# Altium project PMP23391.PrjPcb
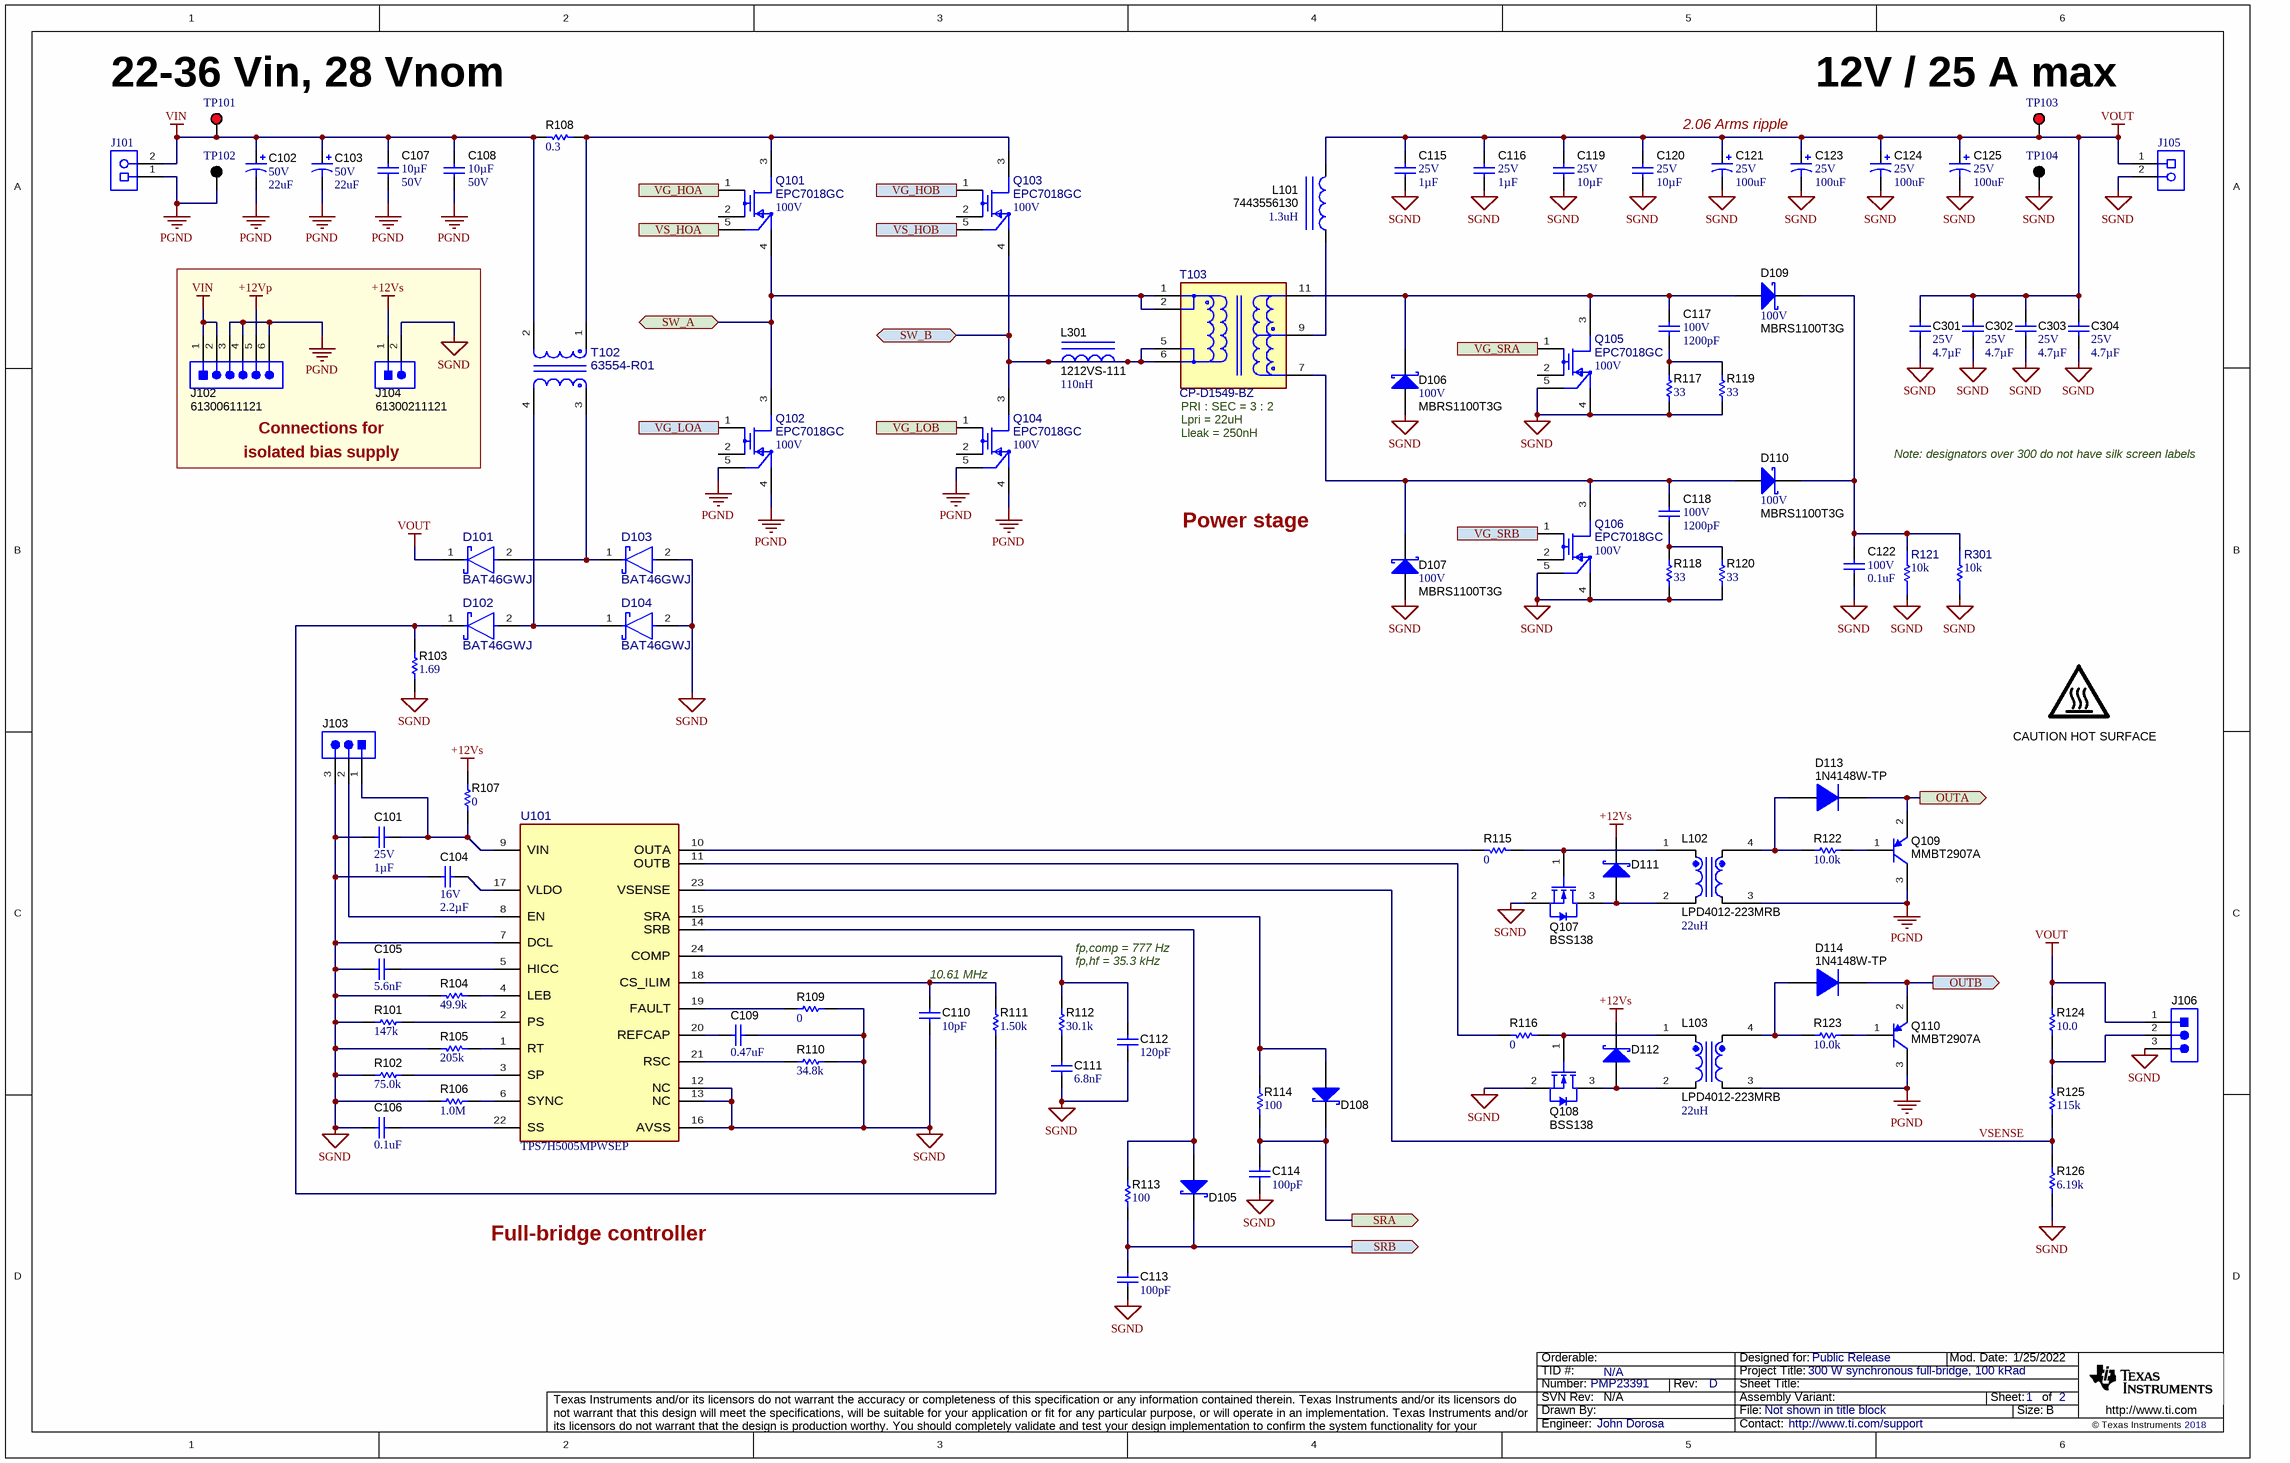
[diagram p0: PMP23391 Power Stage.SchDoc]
TID: N/A; TechSupport: http://www.ti.com/support; SCH_Rev: D; PRJ_Title: 300 W synchronous full-bridge, 100 kRad; PRJ_Number: PMP23391; PRJ_Engineer: John Dorosa; PRJ_Customer: Public Release; PCB_Rev: C; PCB_Layout: John Dorosa; CopyrightYear: 2018
2 sheets, 165 parts. Net scope: flat (ports and power ports of the same name join across sheets).
Board file: PMP23391.PcbDoc
Sheets:
  PMP23391 Power Stage.SchDoc
  PMP23391 Drivers.SchDoc

## Sheet PMP23391 Power Stage.SchDoc
size 431 x 279 mm; Date: Not shown in title block; ApprovedBy: Not shown in title block; CheckedBy: Not shown in title block; Author: Not shown in title block; CompanyName: Not shown in title block; Engineer: Not shown in title block; Organization: Not shown in title block; Address1: Not shown in title block; Address2: Not shown in title block; Address3: Not shown in title block; Address4: Not shown in title block; DocumentNumber: 1; Revision: Use project parameter SCH_Rev; SheetNumber: 1; SheetTotal: 2; PageSetup: Record=PageOptions¦CenterHorizontal=True¦CenterVertical=True¦PrintScale=1.00¦XCorrection=1.00¦YCorrection=1.00¦PrintKind=0¦BorderSize=5000000¦LeftOffset=0¦BottomOffset=0¦Orientation=2¦PaperLength=1000¦PaperWidth=1000¦Scale=100¦PaperSource=15¦PrintQuality=600¦MediaType=1¦DitherType=10¦PaperKind=Letter¦PrintScaleMode=1

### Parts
C101  VDC_V: 25V  Cap_F: 1µF  [0603_HV]  (hidden comment: GRM188R71E105KA12D)
C102  VDC_V: 50V  ValueDisplayed: 22uF  [7343-43]  (hidden comment: T494X226K050AT)
C103  VDC_V: 50V  ValueDisplayed: 22uF  [7343-43]  (hidden comment: T494X226K050AT)
C104  VDC_V: 16V  Cap_F: 2.2µF  [0603_HV]  (hidden comment: GRM188Z71C225KE43)
C105  Cap_F: 5.6nF  [0603_HV]  (hidden comment: GRM188R71E562KA01D)
C106  value 0.1uF  [0603_HV]  (hidden comment: GCM188R71E104KA57D)
C107  ValueDisplayed: 10µF  VDC_V: 50V  [1210_270]  (hidden comment: GCM32EL8EH106KA07L)
C108  ValueDisplayed: 10µF  VDC_V: 50V  [1210_270]  (hidden comment: GCM32EL8EH106KA07L)
C109  value 0.47uF  [0603_HV]  (hidden comment: GCM188R71C474KA55D)
C110  ValueDisplayed: 10pF  [0603_HV]  (hidden comment: GCM1885C2A100JA16D)
C111  Cap_F: 6.8nF  [0603_HV]  (hidden comment: GRM188R71E682KA01D)
C112  ValueDisplayed: 120pF  [0603_HV]  (hidden comment: GRM1885C1H121JA01D)
C113  ValueDisplayed: 100pF  [0603_HV]  (hidden comment: GRM1885C1H101JA01D)
C114  ValueDisplayed: 100pF  [0603_HV]  (hidden comment: GRM1885C1H101JA01D)
C115  VDC_V: 25V  Cap_F: 1µF  [0603_HV]  (hidden comment: GRM188R71E105KA12D)
C116  VDC_V: 25V  Cap_F: 1µF  [0603_HV]  (hidden comment: GRM188R71E105KA12D)
C117  VDC_V: 100V  ValueDisplayed: 1200pF  [0805_HV]  (hidden comment: GRM2165C2A122JA01D)
C118  VDC_V: 100V  ValueDisplayed: 1200pF  [0805_HV]  (hidden comment: GRM2165C2A122JA01D)
C119  VDC_V: 25V  ValueDisplayed: 10µF  [1206]  (hidden comment: GRM31CR71E106MA12L)
C120  VDC_V: 25V  ValueDisplayed: 10µF  [1206]  (hidden comment: GRM31CR71E106MA12L)
C121  VDC_V: 25V  ValueDisplayed: 100uF  [7361-38]  (hidden comment: TPSV107K025R0100)
C122  VDC_V: 100V  ValueDisplayed: 0.1uF  [1206]  (hidden comment: GRM319R72A104KA01D)
C123  VDC_V: 25V  ValueDisplayed: 100uF  [7361-38]  (hidden comment: TPSV107K025R0100)
C124  VDC_V: 25V  ValueDisplayed: 100uF  [7361-38]  (hidden comment: TPSV107K025R0100)
C125  VDC_V: 25V  ValueDisplayed: 100uF  [7361-38]  (hidden comment: TPSV107K025R0100)
C301  VDC_V: 25V  Cap_F: 4.7µF  [0805_HV]  (hidden comment: GRM21BR71E475KA73L)
C302  VDC_V: 25V  Cap_F: 4.7µF  [0805_HV]  (hidden comment: GRM21BR71E475KA73L)
C303  VDC_V: 25V  Cap_F: 4.7µF  [0805_HV]  (hidden comment: GRM21BR71E475KA73L)
C304  VDC_V: 25V  Cap_F: 4.7µF  [0805_HV]  (hidden comment: GRM21BR71E475KA73L)
D101  BAT46GWJ  [FP-BAT46GWJ_SOD-123-MFG]
D102  BAT46GWJ  [FP-BAT46GWJ_SOD-123-MFG]
D103  BAT46GWJ  [FP-BAT46GWJ_SOD-123-MFG]
D104  BAT46GWJ  [FP-BAT46GWJ_SOD-123-MFG]
D105  PMEG4030ER,115  [SOD-123W]  (value not drawn)
D106  MBRS1100T3G  value 100V  [SMB]
D107  MBRS1100T3G  value 100V  [SMB]
D108  PMEG4030ER,115  [SOD-123W]  (value not drawn)
D109  MBRS1100T3G  value 100V  [SMB]
D110  MBRS1100T3G  value 100V  [SMB]
D111  PMEG4030ER,115  [SOD-123W]  (value not drawn)
D112  PMEG4030ER,115  [SOD-123W]  (value not drawn)
D113  1N4148W-TP  [SOD-123]
D114  1N4148W-TP  [SOD-123]
J101  OSTT7020150  [On-Shore_OSTT7020150]  (value not drawn)
J102  61300611121  [WURTH_61300611121]
J103  61300311121  [WURTH_61300311121]  (value not drawn)
J104  61300211121  [WURTH_61300211121]
J105  OSTT7020150  [On-Shore_OSTT7020150]  (value not drawn)
J106  61300311121  [WURTH_61300311121]  (value not drawn)
L101  7443556130  ValueDisplayed: 1.3uH  [WE-HCB_1890]
L102  LPD4012-223MRB  ValueDisplayed: 22uH  [LPD4012]
L103  LPD4012-223MRB  ValueDisplayed: 22uH  [LPD4012]
L301  1212VS-111  ValueDisplayed: 110nH  [SLC1480]
Logo101  CAUTION HOT SURFACE  [IEC_HotSurface_Small]  (no BOM)
Q101  EPC7018GC  VdsMax_V: 100V  [FP-EPC7018GC_FSMD-G-MFG]
Q102  EPC7018GC  VdsMax_V: 100V  [FP-EPC7018GC_FSMD-G-MFG]
Q103  EPC7018GC  VdsMax_V: 100V  [FP-EPC7018GC_FSMD-G-MFG]
Q104  EPC7018GC  VdsMax_V: 100V  [FP-EPC7018GC_FSMD-G-MFG]
Q105  EPC7018GC  VdsMax_V: 100V  [FP-EPC7018GC_FSMD-G-MFG]
Q106  EPC7018GC  VdsMax_V: 100V  [FP-EPC7018GC_FSMD-G-MFG]
Q107  BSS138  [SOT-23]
Q108  BSS138  [SOT-23]
Q109  MMBT2907A  [SOT-23]
Q110  MMBT2907A  [SOT-23]
R101  ValueDisplayed: 147k  [0603_HV]  (hidden comment: CRCW0603147KFKEA)
R102  ValueDisplayed: 75.0k  [0603_HV]  (hidden comment: CRCW060375K0FKEA)
R103  ValueDisplayed: 1.69  [1206]  (hidden comment: CRCW12061R69FKEA)
R104  ValueDisplayed: 49.9k  [0603_HV]  (hidden comment: CRCW060349K9FKEA)
R105  ValueDisplayed: 205k  [0603_HV]  (hidden comment: RC0603FR-07205KL)
R106  ValueDisplayed: 1.0M  [0603_HV]  (hidden comment: CRCW06031M00JNEA)
R107  ValueDisplayed: 0  [0603_HV]  (hidden comment: CRCW06030000Z0EA)
R108  ValueDisplayed: 0.3  [1210]  (hidden comment: MCR25JZHFLR300)
R109  ValueDisplayed: 0  [0603_HV]  (hidden comment: CRCW06030000Z0EA)
R110  ValueDisplayed: 34.8k  [0603_HV]  (hidden comment: CRCW060334K8FKEA)
R111  ValueDisplayed: 1.50k  [0603_HV]  (hidden comment: CRCW06031K50FKEA)
R112  ValueDisplayed: 30.1k  [0603_HV]  (hidden comment: CRCW060330K1FKEA)
R113  ValueDisplayed: 100  [0603_HV]  (hidden comment: CRCW0603100RJNEA)
R114  ValueDisplayed: 100  [0603_HV]  (hidden comment: CRCW0603100RJNEA)
R115  ValueDisplayed: 0  [0805_HV1]  (hidden comment: RC0805JR-070RL)
R116  ValueDisplayed: 0  [0805_HV1]  (hidden comment: RC0805JR-070RL)
R117  ValueDisplayed: 33  [2512]  (hidden comment: CRCW251233R0JNEG)
R118  ValueDisplayed: 33  [2512]  (hidden comment: CRCW251233R0JNEG)
R119  ValueDisplayed: 33  [2512]  (hidden comment: CRCW251233R0JNEG)
R120  ValueDisplayed: 33  [2512]  (hidden comment: CRCW251233R0JNEG)
R121  value 10k  [FP-CRM2512-FX-1002ELF_2512-MFG]  (hidden comment: CRM2512-FX-1002ELF)
R122  ValueDisplayed: 10.0k  [0603_HV]  (hidden comment: CRCW060310K0FKEA)
R123  ValueDisplayed: 10.0k  [0603_HV]  (hidden comment: CRCW060310K0FKEA)
R124  ValueDisplayed: 10.0  [0603_HV]  (hidden comment: CRCW060310R0FKEA)
R125  ValueDisplayed: 115k  [0603_HV]  (hidden comment: CRCW0603115KFKEA)
R126  ValueDisplayed: 6.19k  [0603_HV]  (hidden comment: CRCW06036K19FKEA)
R301  value 10k  [FP-CRM2512-FX-1002ELF_2512-MFG]  (hidden comment: CRM2512-FX-1002ELF)
T102  63554-R01  [FP-63554-R01_SMT_XFRMR_24MM0_20MM0-MFG]
T103  CP-D1549-BZ  [FP-CP-D1549-BZ_SMT_XFRMR_29MM46_26MM67-MFG]
TP101  5010  [Keystone5010]  (value not drawn)
TP102  5011  [Keystone5011]  (value not drawn)
TP103  5010  [Keystone5010]  (value not drawn)
TP104  5011  [Keystone5011]  (value not drawn)
U101  TPS7H5005MPWSEP  [PW0024A-MFG]

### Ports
OUTA (out), OUTB (out), SRA (out), SRB (out), SW_A (bidir), SW_B (bidir), VG_HOA (in), VG_HOB (in), VG_LOA (in), VG_LOB (in), VG_SRA (in), VG_SRB (in), VS_HOA (in), VS_HOB (in)

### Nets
+12Vp: J102.5
+12Vs: D111.1(K) D112.1(K) J104.1 R107.2
PGND: C102.2(-) C103.2(-) C107.2 C108.2 J101.1 J102.3 J102.4 J102.6 L102.3 L103.3 Q102.4(S) Q102.5(SS) Q104.4(S) Q104.5(SS) Q109.3(C) Q110.3(C) TP102.1
SGND: C101.2 C104.1 C105.1 C106.2 C109.1 C110.2 C111.2 C112.2 C113.1 C114.1 C115.2 C116.2 C119.2 C120.2 C121.2(-) C122.2 C123.2(-) C124.2(-) C125.2(-) C301.2 C302.2 C303.2 C304.2 D103.2(ANODE) D104.2(ANODE) D106.2(A) D107.2(A) J103.3 J104.2 J105.2 J106.3 Q105.4(S) Q105.5(SS) Q106.4(S) Q106.5(SS) Q107.2(S) Q108.2(S) R101.1 R102.1 R103.1 R104.2 R105.2 R106.1 R109.2 R110.2 R117.1 R118.1 R119.1 R120.1 R121.2 R126.1 R301.2 TP104.1 U101.7(DCL) U101.12(NC) U101.13(NC) U101.16(AVSS)
VIN: C102.1(+) C103.1(+) C107.1 C108.1 J101.2 J102.1 J102.2 R108.1 T102.2 TP101.1
VOUT: C115.1 C116.1 C119.1 C120.1 C121.1(+) C123.1(+) C124.1(+) C125.1(+) C301.1 C302.1 C303.1 C304.1 D101.1(CATHODE) J105.1 J106.1 L101.2 R124.2 TP103.1
OUTA: D113.1(K) Q109.2(E) ; port OUTA
OUTB: D114.1(K) Q110.2(E) ; port OUTB
SRA: C114.2 D108.1(K) R114.1 ; port SRA
SRB: C113.2 D105.1(K) R113.1 ; port SRB
SW_A: Q101.4(S) Q102.3(D) T103.1 T103.2 ; port SW_A
SW_B: L301.1 L301.2 Q103.4(S) Q104.3(D) T103.5 T103.6 ; port SW_B
VG_HOA: Q101.1(G) ; port VG_HOA
VG_HOB: Q103.1(G) ; port VG_HOB
VG_LOA: Q102.1(G) ; port VG_LOA
VG_LOB: Q104.1(G) ; port VG_LOB
VG_SRA: Q105.1(G) ; port VG_SRA
VG_SRB: Q106.1(G) ; port VG_SRB
VS_HOA: Q101.5(SS) ; port VS_HOA
VS_HOB: Q103.5(SS) ; port VS_HOB
VSENSE: R125.1 R126.2 U101.23(VSENSE)
NetC101_1: C101.1 J103.1 R107.1 U101.9(VIN)
NetC104_2: C104.2 U101.17(VLDO)
NetC105_2: C105.2 U101.5(HICC)
NetC106_1: C106.1 U101.22(SS)
NetC109_2: C109.2 U101.20(REFCAP)
NetC110_1: C110.1 R111.1 U101.18(CS_ILIM)
NetC111_1: C111.1 R112.1
NetC112_1: C112.1 R112.2 U101.24(COMP)
NetC117_1: C117.1 D106.1(K) D109.2(A) Q105.3(D) T103.11
NetC117_2: C117.2 R117.2 R119.2
NetC118_1: C118.1 D107.1(K) D110.2(A) Q106.3(D) T103.7
NetC118_2: C118.2 R118.2 R120.2
NetC122_1: C122.1 D109.1(K) D110.1(K) R121.1 R301.1
NetD101_2: D101.2(ANODE) D103.1(CATHODE) T102.3
NetD102_1: D102.1(CATHODE) R103.2 R111.2
NetD102_2: D102.2(ANODE) D104.1(CATHODE) T102.4
NetD105_2: D105.2(A) R113.2 U101.14(SRB)
NetD108_2: D108.2(A) R114.2 U101.15(SRA)
NetD111_2: D111.2(A) L102.2 Q107.3(D)
NetD112_2: D112.2(A) L103.2 Q108.3(D)
NetD113_2: D113.2(A) L102.4 R122.2
NetD114_2: D114.2(A) L103.4 R123.2
NetJ103_2: J103.2 U101.8(EN)
NetJ106_2: J106.2 R124.1 R125.2
NetL101_1: L101.1 T103.9
NetL102_1: L102.1 Q107.1(G) R115.1
NetL103_1: L103.1 Q108.1(G) R116.1
NetQ101_3: Q101.3(D) Q103.3(D) R108.2 T102.1
NetQ109_1: Q109.1(B) R122.1
NetQ110_1: Q110.1(B) R123.1
NetR101_2: R101.2 U101.2(PS)
NetR102_2: R102.2 U101.3(SP)
NetR104_1: R104.1 U101.4(LEB)
NetR105_1: R105.1 U101.1(RT)
NetR106_2: R106.2 U101.6(SYNC)
NetR109_1: R109.1 U101.19(FAULT)
NetR110_1: R110.1 U101.21(RSC)
NetR115_2: R115.2 U101.10(OUTA)
NetR116_2: R116.2 U101.11(OUTB)

Not connected (* = marked no-connect by the designer): Q101 2(G); Q102 2(G); Q103 2(G); Q104 2(G); Q105 2(G); Q106 2(G)

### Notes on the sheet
- (near TP101) 22-36 Vin, 28 Vnom
- (near TP103) 12V / 25 A max
- 2.06 Arms ripple
- Connections for
- (near T103) PRI : SEC = 3 : 2
- (near T103) Lpri = 22uH
- isolated bias supply
- Lleak = 250nH
- Note: designators over 300 do not have silk screen labels
- Power stage
- fp,comp = 777 Hz
- 10.61 MHz
- fp,hf = 35.3 kHz
- Full-bridge controller

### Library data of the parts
C101 C115 C116 = CMP-0007405-5: CAP, CERM, 1 uF, 25 V, +/- 10%, X7R, 0603; Manufacturer: MuRata; Cap_Case: 0603; AEC Category: Q200; Value: 1uF; SizeX_mm: 1.6; U/M: EA; Value1: Unknown; SizeAreaWB_mm2: 4.68; SizeY_mm: 0.8; TaMin_C: -55°C; SizeZ_mm: 1; Polarized: N; MFG_Status: TI_Obsolete; TaMax_C: 125°C; SizeArea_mm2: 1.28
C102 C103 = CMP-0011753-2: CAP, TA, 22 uF, 50 V, +/- 10%, 0.5 ohm, SMD; Manufacturer: Kemet; TaMin_C: -55°C; ESR_ohm: 0.5; Polarized: Y; SizeAreaWB_mm2: 58.59; Value1: 0.5 ohm; U/M: EA; Value: 22uF; TaMax_C: 125°C; SizeZ_mm: 4.3; SizeX_mm: 7.3; SizeArea_mm2: 31.39; CompType: Capacitor; AEC Qualified: N; Cap_F: 22µF; IRMS_A: 574mA; AEC Category: Q200
C104 = CMP-0007499-4: CAP, CERM, 2.2 uF, 16 V, +/- 10%, X7R, 0603; Manufacturer: MuRata; TaMin_C: -55°C; Polarized: N; SizeAreaWB_mm2: 4.68; Value1: Unknown; U/M: EA; Value: 2.2uF; TaMax_C: 125°C; SizeZ_mm: 1; SizeX_mm: 1.6; SizeY_mm: 0.8; Cap_Case: 0603; SizeArea_mm2: 1.28; AEC Category: Q200
C105 = CMP-0007425-5: CAP, CERM, 5600 pF, 25 V, +/- 10%, X7R, 0603; Manufacturer: MuRata; ValueDisplayed: 5600pF; SizeArea_mm2: 1.28; SizeZ_mm: 1; Value2: 25V; MFG_Status: TI_Obsolete; SizeX_mm: 1.6; Value1: Unknown; AEC Category: Q200; Value: 5600pF; SizeAreaWB_mm2: 4.68; Polarized: N; Cap_Case: 0603; U/M: EA; TaMin_C: -55°C; TaMax_C: 125°C; SizeY_mm: 0.8
C106 = CMP-0084679-1: CAP, CERM, 0.1 µF, 25 V,+/- 10%, X7R, AEC-Q200 Grade 1, 0603; Manufacturer: MuRata; VDC_V: 25V; TaMin_C: -55°C; SizeY_mm: 0.8; Polarized: N; SizeArea_mm2: 1.28; Cap_Case: 0603; SizeZ_mm: 1; SizeX_mm: 1.6; AEC Qualified: Y; AEC Category: Q200; ValueDisplayed: 0.1µF; TaMax_C: 125°C; U/M: EA; SizeAreaWB_mm2: 4.68; Cap_F: 100nF
C107 C108 = CMP-0860266-1: CAP, CERM, 10 µF, 50 V,+/- 10%, X8L, AEC-Q200 Grade 0, 1210; Manufacturer: MuRata; Value: 10uF; U/M: EA; SizeY_mm: 2.5; Polarized: N; AEC Category: Q200; SizeZ_mm: 2.7; TaMin_C: -55°C; AEC Qualified: Y; TaMax_C: 150°C; Cap_Case: 1210; SizeArea_mm2: 8; SizeAreaWB_mm2: 14.7; AEC Grade: 0; SizeX_mm: 3.2
C109 = CMP-0007138-4: CAP, CERM, 0.47 uF, 16 V, +/- 10%, X7R, AEC-Q200 Grade 1, 0603; Manufacturer: MuRata; TaMin_C: -55°C; Polarized: N; SizeAreaWB_mm2: 4.68; Value1: Unknown; U/M: EA; TaMax_C: 125°C; SizeZ_mm: 1; SizeX_mm: 1.6; SizeY_mm: 0.8; Cap_Case: 0603; Value2: 16V; SizeArea_mm2: 1.28; AEC Qualified: Y; Cap_F: 470nF; AEC Category: Q200
C110 = CMP-0084283-1: CAP, CERM, 10 pF, 100 V,+/- 5%, C0G/NP0, AEC-Q200 Grade 1, 0603; Manufacturer: MuRata; TaMax_C: 125°C; Cap_Case: 0603; Value2: 100V; SizeX_mm: 1.6; SizeY_mm: 0.8; SizeArea_mm2: 1.28; Polarized: N; AEC Category: Q200; SizeAreaWB_mm2: 4.68; AEC Qualified: Y; SizeZ_mm: 1; Value: 10pF; U/M: EA; TaMin_C: -55°C
C111 = CMP-0007427-5: CAP, CERM, 6800 pF, 25 V, +/- 10%, X7R, 0603; Manufacturer: MuRata; Value1: Unknown; MFG_Status: TI_Obsolete; SizeY_mm: 0.8; TaMin_C: -55°C; Value2: 25V; U/M: EA; SizeAreaWB_mm2: 4.68; SizeArea_mm2: 1.28; AEC Category: Q200; SizeZ_mm: 1; ValueDisplayed: 6800pF; Polarized: N; SizeX_mm: 1.6; TaMax_C: 125°C; Cap_Case: 0603; Value: 6800pF
C112 = CMP-0007179-4: CAP, CERM, 120 pF, 50 V, +/- 5%, C0G/NP0, 0603; Manufacturer: MuRata; TaMin_C: -55°C; Polarized: N; SizeAreaWB_mm2: 4.68; Value1: Unknown; U/M: EA; Value: 120pF; TaMax_C: 125°C; SizeZ_mm: 1; SizeX_mm: 1.6; SizeY_mm: 0.8; Cap_Case: 0603; Value2: 50V; SizeArea_mm2: 1.28; AEC Category: Q200
C113 C114 = CMP-0007171-4: CAP, CERM, 100 pF, 50 V, +/- 5%, C0G/NP0, 0603; Manufacturer: MuRata; TaMin_C: -55°C; Polarized: N; SizeAreaWB_mm2: 4.68; Value1: Unknown; U/M: EA; Value: 100pF; TaMax_C: 125°C; SizeZ_mm: 1; SizeX_mm: 1.6; SizeY_mm: 0.8; Cap_Case: 0603; Value2: 50V; SizeArea_mm2: 1.28; AEC Category: Q200
C117 C118 = CMP-0008098-2: CAP, CERM, 1200 pF, 100 V, +/- 5%, C0G/NP0, 0805; Manufacturer: MuRata; TaMin_C: -55°C; Polarized: N; SizeAreaWB_mm2: 6.75; Value1: Unknown; U/M: EA; Value: 1200pF; TaMax_C: 125°C; SizeZ_mm: 1.45; SizeX_mm: 2; SizeY_mm: 1.25; Cap_Case: 0805; SizeArea_mm2: 2.5; Cap_F: 1.2nF; AEC Category: Q200
C119 C120 = CMP-0082252-1: CAP, CERM, 10 µF, 25 V,+/- 20%, X7R, AEC-Q200 Grade 1, 1206; Manufacturer: MuRata; SizeAreaWB_mm2: 10.92; SizeArea_mm2: 5.12; AEC Qualified: Y; AEC Category: Q200; Value: 10uF; TaMax_C: 125°C; SizeZ_mm: 1.35; AEC Grade: 1; Polarized: N; TaMin_C: -55°C; SizeY_mm: 1.6; U/M: EA; SizeX_mm: 3.2
C121 C123-C125 = CMP-0012041-2: CAP, TA, 100 uF, 25 V, +/- 10%, 0.1 ohm, SMD; Manufacturer: AVX; TaMin_C: -55°C; ESR_ohm: 0.1; Polarized: Y; SizeAreaWB_mm2: 75.33; Value1: 0.1 ohm; U/M: EA; Value: 100uF; TaMax_C: 125°C; SizeZ_mm: 3.8; SizeX_mm: 7.3; SizeY_mm: 6.1; SizeArea_mm2: 44.53; CompType: Capacitor; Cap_F: 100µF; IRMS_A: 1.423A; AEC Category: Q200
C122 = CMP-0008881-2: CAP, CERM, 0.1 uF, 100 V, +/- 10%, X7R, 1206; Manufacturer: MuRata; TaMin_C: -55°C; Polarized: N; SizeAreaWB_mm2: 10.92; Value1: Unknown; U/M: EA; Value: 0.1uF; TaMax_C: 125°C; SizeZ_mm: 1.35; SizeX_mm: 3.2; SizeY_mm: 1.6; SizeArea_mm2: 5.12; Cap_F: 100nF; AEC Category: Q200
C301-C304 = CMP-0008346-3: CAP, CERM, 4.7 uF, 25 V, +/- 10%, X7R, 0805; Manufacturer: MuRata; TaMax_C: 125°C; SizeZ_mm: 1.45; Value1: Unknown; Polarized: N; SizeY_mm: 1.25; TaMin_C: -55°C; SizeX_mm: 2; SizeAreaWB_mm2: 6.75; MFG_Status: TI_Obsolete; SizeArea_mm2: 2.5; AEC Category: Q200; Cap_Case: 0805; Value: 4.7uF; U/M: EA
D101-D104 = CMP-0090343-1: Diode Schottky 100V 250mA (DC) Surface Mount SOD-123; Manufacturer: Nexperia; SizeZ_mm: 1.3mm; Peak Reverse Current: 2uA; TaMin_C: -55°C; Cap_F: 39pF; TJmax_C: 150°C; AEC Grade: Grade 0; Max Surge Forward Current: 2.5A; Standoff Height: 0mm; TaMax_C: +150°C; AEC Qualified: Yes
D105 D108 D111 D112 = CMP-0080763-2: Diode, Schottky, 40 V, 3 A, AEC-Q101, SOD-123W; Manufacturer: Nexperia; Value2: 0.54V; AEC Category: Q101; SizeArea_mm2: 5.95; AEC Qualified: Y; Io_A: 3A; SizeZ_mm: 1; Value: 40V; SizeY_mm: 1.7; Vf_V: 540mV; SizeAreaWB_mm2: 12.15; SizeX_mm: 3.5; TJmax_C: 150°C
D106 D107 D109 D110 = CMP-0028521-2: Diode, Schottky, 100 V, 1 A, SMB; Manufacturer: ON Semiconductor; TJmax_C: 150°C; SizeY_mm: 3.81; RJC_CperW: 22; Value1: 1A; SizeAreaWB_mm2: 44.156; Green_Lifecycle: Active; SizeArea_mm2: 21.336; Vf_V: 750mV; SizeZ_mm: 2.6; SizeX_mm: 5.6; Green_REACh: Passed; Value2: 0.75V; AEC Category: Q101
D113 D114 = CMP-0076974-2: Diode, Switching, 100 V, 0.15 A, SOD-123; Manufacturer: Micro Commercial Components; Io_A: 150mA; SizeX_mm: 3.85; SizeY_mm: 1.7; Green_REACh: Incomplete; AEC Category: Q101; TJmax_C: 150°C; Value1: 0.15A; Vf_V: 1.25V; Value: 100V; SizeZ_mm: 1.35; SizeArea_mm2: 6.545; SizeAreaWB_mm2: 13.095; Green_Lifecycle: Not Set
J101 J105 = CMP-0075360-1: Terminal Block, 6.35mm, 2x1, TH; Manufacturer: On-Shore Technology; CNHeader: False; Current_A: 30A; Gender: Female; Cert_CULUS: Y; Voltage_V: 300V; Row_Count: 1; Pitch_mm: 6.35; CT: True
J102 = CMP-0054801-2: Header, 2.54 mm, 6x1, Gold, TH; Manufacturer: Wurth Elektronik; Cert_UL: Y; Gender: Male; Row_Count: 1; Shrouded: N; Pitch_mm: 2.54
J103 J106 = CMP-0054796-4: Header, 2.54 mm, 3x1, Gold, TH; Manufacturer: Wurth Elektronik; Green_REACh: Passed; CT: FALSE; CNHeader: TRUE; Green_Lifecycle: Active
J104 = CMP-0054794-2: Header, 2.54 mm, 2x1, Gold, TH; Manufacturer: Wurth Elektronik; Shrouded: N; Gender: Male; Green_REACh: Passed; Pitch_mm: 2.54; Green_Lifecycle: Active; Row_Count: 1; Cert_UL: Y
L101 = CMP-0064040-1: Inductor, Shielded Drum Core, WE-Superflux200, 1.3 uH, 34.5 A, 0.0009 ohm, SMD; Manufacturer: Wurth Elektronik; Isat: 62A @ 30% inductance drop; Irms: 34.5A @ 50C rise; Green_Lifecycle: Active; SizeAreaWB_mm2: 410.06; DCR_ohm: 900µ; Green_REACh: Passed; Value: 1.3uH; Imax_A: 34.5A; SizeZ_mm: 9.2; SizeX_mm: 18.3; SizeY_mm: 18.2; SizeArea_mm2: 333.06; Ind_H: 1.3µH; AEC Category: Q200
L102 L103 = CMP-0012812-2: Coupled inductor, 22 uH, 0.7 A, 1.63 ohm, TH; Manufacturer: Coilcraft; SizeAreaWB_mm2: 25; DCR_ohm: 1.63; Value: 22uH; SizeZ_mm: 1.2; SizeX_mm: 4; SizeArea_mm2: 16; Ind_H: 22µH
L301 = CMP-0060882-1: Inductor, Unshielded, Air core, 110 nH, 44 A, 0.0015 ohm, SMD; Manufacturer: Coilcraft; PartNumber: SLC1480-111MLB; Isat: 130A @ 30% inductance drop; Irms: 55A @ 40C rise; Green_Lifecycle: Not Set; SizeAreaWB_mm2: 231.127; DCR_ohm: 150µ; Green_REACh: Incomplete; Value1: 0.00015 ohm; Material: Ferrite; Value: 110nH; Imax_A: 55A; SizeZ_mm: 8; SizeX_mm: 13.46; SizeY_mm: 12.95; SizeArea_mm2: 174.307; AEC Category: Q200
Logo101 = CMP-0074837-2: IEC 61010-1 Hot Surface Warning; Manufacturer: Texas Instruments; CompType: IC; AEC Category: Q200; SymbolCreator: a0412235
Q101-Q106 = CMP-0047628-1: MOSFET N-Channel 100 V 80A (Tc) Surface Mount 5-SMD; Manufacturer: EPC Space; AEC Qualified: No; QgTyp_nC: 11.7nC @ 5V; Rdson45_ohm: 5.2m; SizeZ_mm: 2.235mm; Vgs_V: 6V; ChMode: False; Input Capacitace At Vds: 1240pF @ 50V; Number Of Channels: 1; Pulse Drain Current: 345A; Rthja Max: 48°C/W; Threshold Vgs Max: 2.5V; Threshold Vgs Min: 0.8V; TJmax_C: +150°C
Q107 Q108 = CMP-0000755-1: MOSFET, N-CH, 50 V, 0.22 A, SOT-23; Alternate Manufacturer: None; Manufacturer: Fairchild Semiconductor; SizeZ_mm: 1.1; ChType: N; Value2: 1.7 nC; VdsMax_V: 50V; SizeX_mm: 2.5; SizeY_mm: 3; Vgs_V: 20V; Value: 50V; Rdson45_ohm: 6; SizeArea_mm2: 7.5; AEC Category: Q101; IdsMax_A: 220mA; SizeAreaWB_mm2: 14; U/M: EA; QgTyp_nC: 1.7
Q109 Q110 = CMP-0000331-2: Transistor, PNP, 60 V, 0.8 A, SOT-23; Manufacturer: Fairchild Semiconductor; TaMax_C: 150°C; Value2: 300; Value1: 0.8 A; Vcesat1_V: 1.6V; SizeX_mm: 2.5; SizeY_mm: 3; TaMin_C: -55°C; IcRated_A: 800mA; CompType: BJT; SizeZ_mm: 1.1; Value: 60 V; SizeArea_mm2: 7.5; NPN: 0; Vceo_V: 60V; PNP: 1; AEC Category: Q101; SizeAreaWB_mm2: 14; U/M: EA
R101 = CMP-0022052-4: RES, 147 k, 1%, 0.1 W, AEC-Q200 Grade 0, 0603; Manufacturer: Vishay-Dale; Power_W: 100mW; TempCo: 100 ppm/C; Value: 147k; EIA_Code: E96; SizeX_mm: 1.6; SizeY_mm: 0.8; SizeZ_mm: 1; Value2: 0.1W; SizeArea_mm2: 1.28; AEC Qualified: Y; VDC_V: 75V; AEC Category: Q200; AEC Grade: 0
R102 = CMP-0022589-4: RES, 75.0 k, 1%, 0.1 W, AEC-Q200 Grade 0, 0603; Manufacturer: Vishay-Dale; Power_W: 100mW; TempCo: 100 ppm/C; Value_Code: 75k0; Value: 75.0k; EIA_Code: E96; Res_ohm: 75k; SizeX_mm: 1.6; SizeY_mm: 0.8; SizeZ_mm: 1; Value2: 0.1W; SizeArea_mm2: 1.28; AEC Qualified: Y; VDC_V: 75V; AEC Category: Q200; AEC Grade: 0
R103 = CMP-0016768-3: RES, 1.69, 1%, 0.25 W, AEC-Q200 Grade 0, 1206; Manufacturer: Vishay-Dale; Power_W: 250mW; TempCo: 100 ppm/C; Value_Code: 1R69; Value: 1.69; EIA_Code: E96; SizeX_mm: 3.2; SizeY_mm: 1.6; SizeZ_mm: 1.35; Value2: 0.25W; SizeArea_mm2: 5.12; AEC Qualified: Y; VDC_V: 200V; AEC Category: Q200; AEC Grade: 0
R104 = CMP-0022447-4: RES, 49.9 k, 1%, 0.1 W, AEC-Q200 Grade 0, 0603; Manufacturer: Vishay-Dale; Power_W: 100mW; TempCo: 100 ppm/C; Value_Code: 49k9; Value: 49.9k; EIA_Code: E96; SizeX_mm: 1.6; SizeY_mm: 0.8; SizeZ_mm: 1; Value2: 0.1W; SizeArea_mm2: 1.28; AEC Qualified: Y; VDC_V: 75V; AEC Category: Q200; AEC Grade: 0
R105 = CMP-0022903-4: RES, 205 k, 1%, 0.1 W, 0603; Manufacturer: Yageo; Power_W: 100mW; TempCo: 100 ppm/C; Value: 205k; EIA_Code: E96; SizeX_mm: 1.6; SizeY_mm: 0.8; SizeZ_mm: 1; Value2: 0.1W; SizeArea_mm2: 1.28; AEC Qualified: N; VDC_V: 75V; AEC Category: Q200; SizeAreaWB_mm2: 4.68
R106 = CMP-0025736-4: RES, 1.0 M, 5%, 0.1 W, AEC-Q200 Grade 0, 0603; Manufacturer: Vishay-Dale; Power_W: 100mW; TempCo: 200 ppm/C; Value_Code: 1M00; Value: 1.0Meg; EIA_Code: E24; Res_ohm: 1M; SizeX_mm: 1.6; SizeY_mm: 0.8; SizeZ_mm: 1; Value2: 0.1W; SizeArea_mm2: 1.28; AEC Qualified: Y; VDC_V: 75V; AEC Category: Q200; AEC Grade: 0
R107 R109 = CMP-0025697-4: RES, 0, 5%, 0.1 W, AEC-Q200 Grade 0, 0603; Manufacturer: Vishay-Dale; Power_W: 100mW; TempCo: 200 ppm/C; Value_Code: 0000; Value: 0; EIA_Code: E24; SizeX_mm: 1.6; SizeY_mm: 0.8; SizeZ_mm: 1; Value2: 0.1W; SizeArea_mm2: 1.28; AEC Qualified: Y; VDC_V: 75V; AEC Category: Q200
R108 = CMP-0015178-2: RES, 0.3, 1%, 0.5 W, 1210; Manufacturer: Rohm; Power_W: 500mW; TempCo: 200 ppm/C; SizeAreaWB_mm2: 14.7; Value_Code: R300; U/M: EA; Value: 0.3; EIA_Code: E96; SizeX_mm: 3.2; SizeY_mm: 2.5; SizeZ_mm: 1.35; Value2: 0.5W; SizeArea_mm2: 8; VDC_V: 0V; AEC Category: Q200
R110 = CMP-0022347-4: RES, 34.8 k, 1%, 0.1 W, AEC-Q200 Grade 0, 0603; Manufacturer: Vishay-Dale; Power_W: 100mW; TempCo: 100 ppm/C; Value_Code: 34k8; Value: 34.8k; EIA_Code: E96; SizeX_mm: 1.6; SizeY_mm: 0.8; SizeZ_mm: 1; Value2: 0.1W; SizeArea_mm2: 1.28; AEC Qualified: Y; VDC_V: 75V; AEC Category: Q200; AEC Grade: 0
R111 = CMP-0022126-4: RES, 1.50 k, 1%, 0.1 W, AEC-Q200 Grade 0, 0603; Manufacturer: Vishay-Dale; Power_W: 100mW; TempCo: 100 ppm/C; Value_Code: 1k50; Value: 1.50k; EIA_Code: E96; Res_ohm: 1.5k; SizeX_mm: 1.6; SizeY_mm: 0.8; SizeZ_mm: 1; Value2: 0.1W; SizeArea_mm2: 1.28; AEC Qualified: Y; VDC_V: 75V; AEC Category: Q200; AEC Grade: 0
R112 = CMP-0022324-4: RES, 30.1 k, 1%, 0.1 W, AEC-Q200 Grade 0, 0603; Manufacturer: Vishay-Dale; Power_W: 100mW; TempCo: 100 ppm/C; Value_Code: 30k1; Value: 30.1k; EIA_Code: E96; SizeX_mm: 1.6; SizeY_mm: 0.8; SizeZ_mm: 1; Value2: 0.1W; SizeArea_mm2: 1.28; AEC Qualified: Y; VDC_V: 75V; AEC Category: Q200; AEC Grade: 0
R113 R114 = CMP-0025700-4: RES, 100, 5%, 0.1 W, AEC-Q200 Grade 0, 0603; Manufacturer: Vishay-Dale; Power_W: 100mW; TempCo: 200 ppm/C; Value_Code: 100R; Value: 100; EIA_Code: E24; SizeX_mm: 1.6; SizeY_mm: 0.8; SizeZ_mm: 1; Value2: 0.1W; SizeArea_mm2: 1.28; AEC Qualified: Y; VDC_V: 75V; AEC Category: Q200; AEC Grade: 0
R115 R116 = CMP-0020803-2: RES, 0, 5%, 0.125 W, 0805; Manufacturer: Yageo America; Power_W: 125mW; TempCo: 200 ppm/C; Value_Code: 0000; U/M: EA; Value: 0; EIA_Code: E24; SizeX_mm: 2; SizeY_mm: 1.25; SizeZ_mm: 1.45; Value2: 0.125W; SizeArea_mm2: 2.5; VDC_V: 150V; AEC Category: Q200
R117-R120 = CMP-0015945-3: RES, 33, 5%, 1 W, AEC-Q200 Grade 0, 2512; Manufacturer: Vishay-Dale; Power_W: 1W; TempCo: 200 ppm/C; Value_Code: 33R0; Value: 33; EIA_Code: E24; SizeX_mm: 6.3; SizeY_mm: 3.2; SizeZ_mm: 0.71; SizeArea_mm2: 20.16; AEC Qualified: Y; VDC_V: 500V; AEC Grade: 0; AEC Category: Q200
R121 R301 = CMP-0122385-1: 10 kOhms ±1% 2W Chip Resistor 2512 (6432 Metric) Current Sense Thick Film; Manufacturer: Bourns; AEC Qualified: No; SizeZ_mm: 0.8mm; TempCo: 100ppm/°C; VDC_V: 300V
R122 R123 = CMP-0021998-4: RES, 10.0 k, 1%, 0.1 W, AEC-Q200 Grade 0, 0603; Manufacturer: Vishay-Dale; Power_W: 100mW; TempCo: 100 ppm/C; Value_Code: 10k0; Value: 10.0k; EIA_Code: E96; Res_ohm: 10k; SizeX_mm: 1.6; SizeY_mm: 0.8; SizeZ_mm: 1; Value2: 0.1W; SizeArea_mm2: 1.28; AEC Qualified: Y; VDC_V: 75V; AEC Category: Q200; AEC Grade: 0
R124 = CMP-0022003-4: RES, 10.0, 1%, 0.1 W, AEC-Q200 Grade 0, 0603; Manufacturer: Vishay-Dale; Power_W: 100mW; TempCo: 100 ppm/C; Value_Code: 10R0; Value: 10.0; EIA_Code: E96; Res_ohm: 10; SizeX_mm: 1.6; SizeY_mm: 0.8; SizeZ_mm: 1; Value2: 0.1W; SizeArea_mm2: 1.28; AEC Qualified: Y; VDC_V: 75V; AEC Category: Q200; AEC Grade: 0
R125 = CMP-0022012-4: RES, 115 k, 1%, 0.1 W, AEC-Q200 Grade 0, 0603; Manufacturer: Vishay-Dale; Power_W: 100mW; TempCo: 100 ppm/C; Value: 115k; EIA_Code: E96; SizeX_mm: 1.6; SizeY_mm: 0.8; SizeZ_mm: 1; Value2: 0.1W; SizeArea_mm2: 1.28; AEC Qualified: Y; VDC_V: 75V; AEC Category: Q200; AEC Grade: 0
R126 = CMP-0022559-4: RES, 6.19 k, 1%, 0.1 W, AEC-Q200 Grade 0, 0603; Manufacturer: Vishay-Dale; Power_W: 100mW; TempCo: 100 ppm/C; Value_Code: 6k19; Value: 6.19k; EIA_Code: E96; SizeX_mm: 1.6; SizeY_mm: 0.8; SizeZ_mm: 1; Value2: 0.1W; SizeArea_mm2: 1.28; AEC Qualified: Y; VDC_V: 75V; AEC Category: Q200; AEC Grade: 0
T102 = CMP-0122471-1: Current Transformer 1:50; Manufacturer: Payton Planar; SizeZ_mm: 9mm; AEC Qualified: No
T103 = CMP-0122726-1: Transformer Vin-22-36V/500KHz/Full-Bridge, Vo=12V/26A Isolation=1500V, T/R=3:2; Manufacturer: Coilcraft; Ind_H: 22µH; Ns1toNp: 3:2; SizeZ_mm: 17.04mm; AEC Qualified: No; Voltage_Isolation_Vrms: 1.5kV
TP101 TP103 = CMP-0055147-2: Test Point, Multipurpose, Red, TH; Manufacturer: Keystone Electronics; CT: TRUE; ContactFinish: Silver; Green_Lifecycle: Active; CNHeader: FALSE; Green_REACh: Passed
TP102 TP104 = CMP-0055148-2: Test Point, Multipurpose, Black, TH; Manufacturer: Keystone Electronics; CNHeader: FALSE; ContactFinish: Silver; Green_REACh: Passed; Green_Lifecycle: Active; CT: TRUE
U101 = CMP-0092938-1: Manufacturer: Texas Instruments; AEC Qualified: No; SizeZ_mm: 1.2mm; Standoff Height: 0.05mm

## Sheet PMP23391 Drivers.SchDoc
size 431 x 279 mm; Date: Not shown in title block; ApprovedBy: Not shown in title block; CheckedBy: Not shown in title block; Author: Not shown in title block; CompanyName: Not shown in title block; Engineer: Not shown in title block; Organization: Not shown in title block; Address1: Not shown in title block; Address2: Not shown in title block; Address3: Not shown in title block; Address4: Not shown in title block; DocumentNumber: 2; Revision: Use project parameter SCH_Rev; SheetNumber: 2; SheetTotal: 2; PageSetup: Record=PageOptions¦CenterHorizontal=True¦CenterVertical=True¦PrintScale=1.00¦XCorrection=1.00¦YCorrection=1.00¦PrintKind=0¦BorderSize=5000000¦LeftOffset=0¦BottomOffset=0¦Orientation=2¦PaperLength=1000¦PaperWidth=1000¦Scale=100¦PaperSource=15¦PrintQuality=600¦MediaType=1¦DitherType=10¦PaperKind=Letter¦PrintScaleMode=1
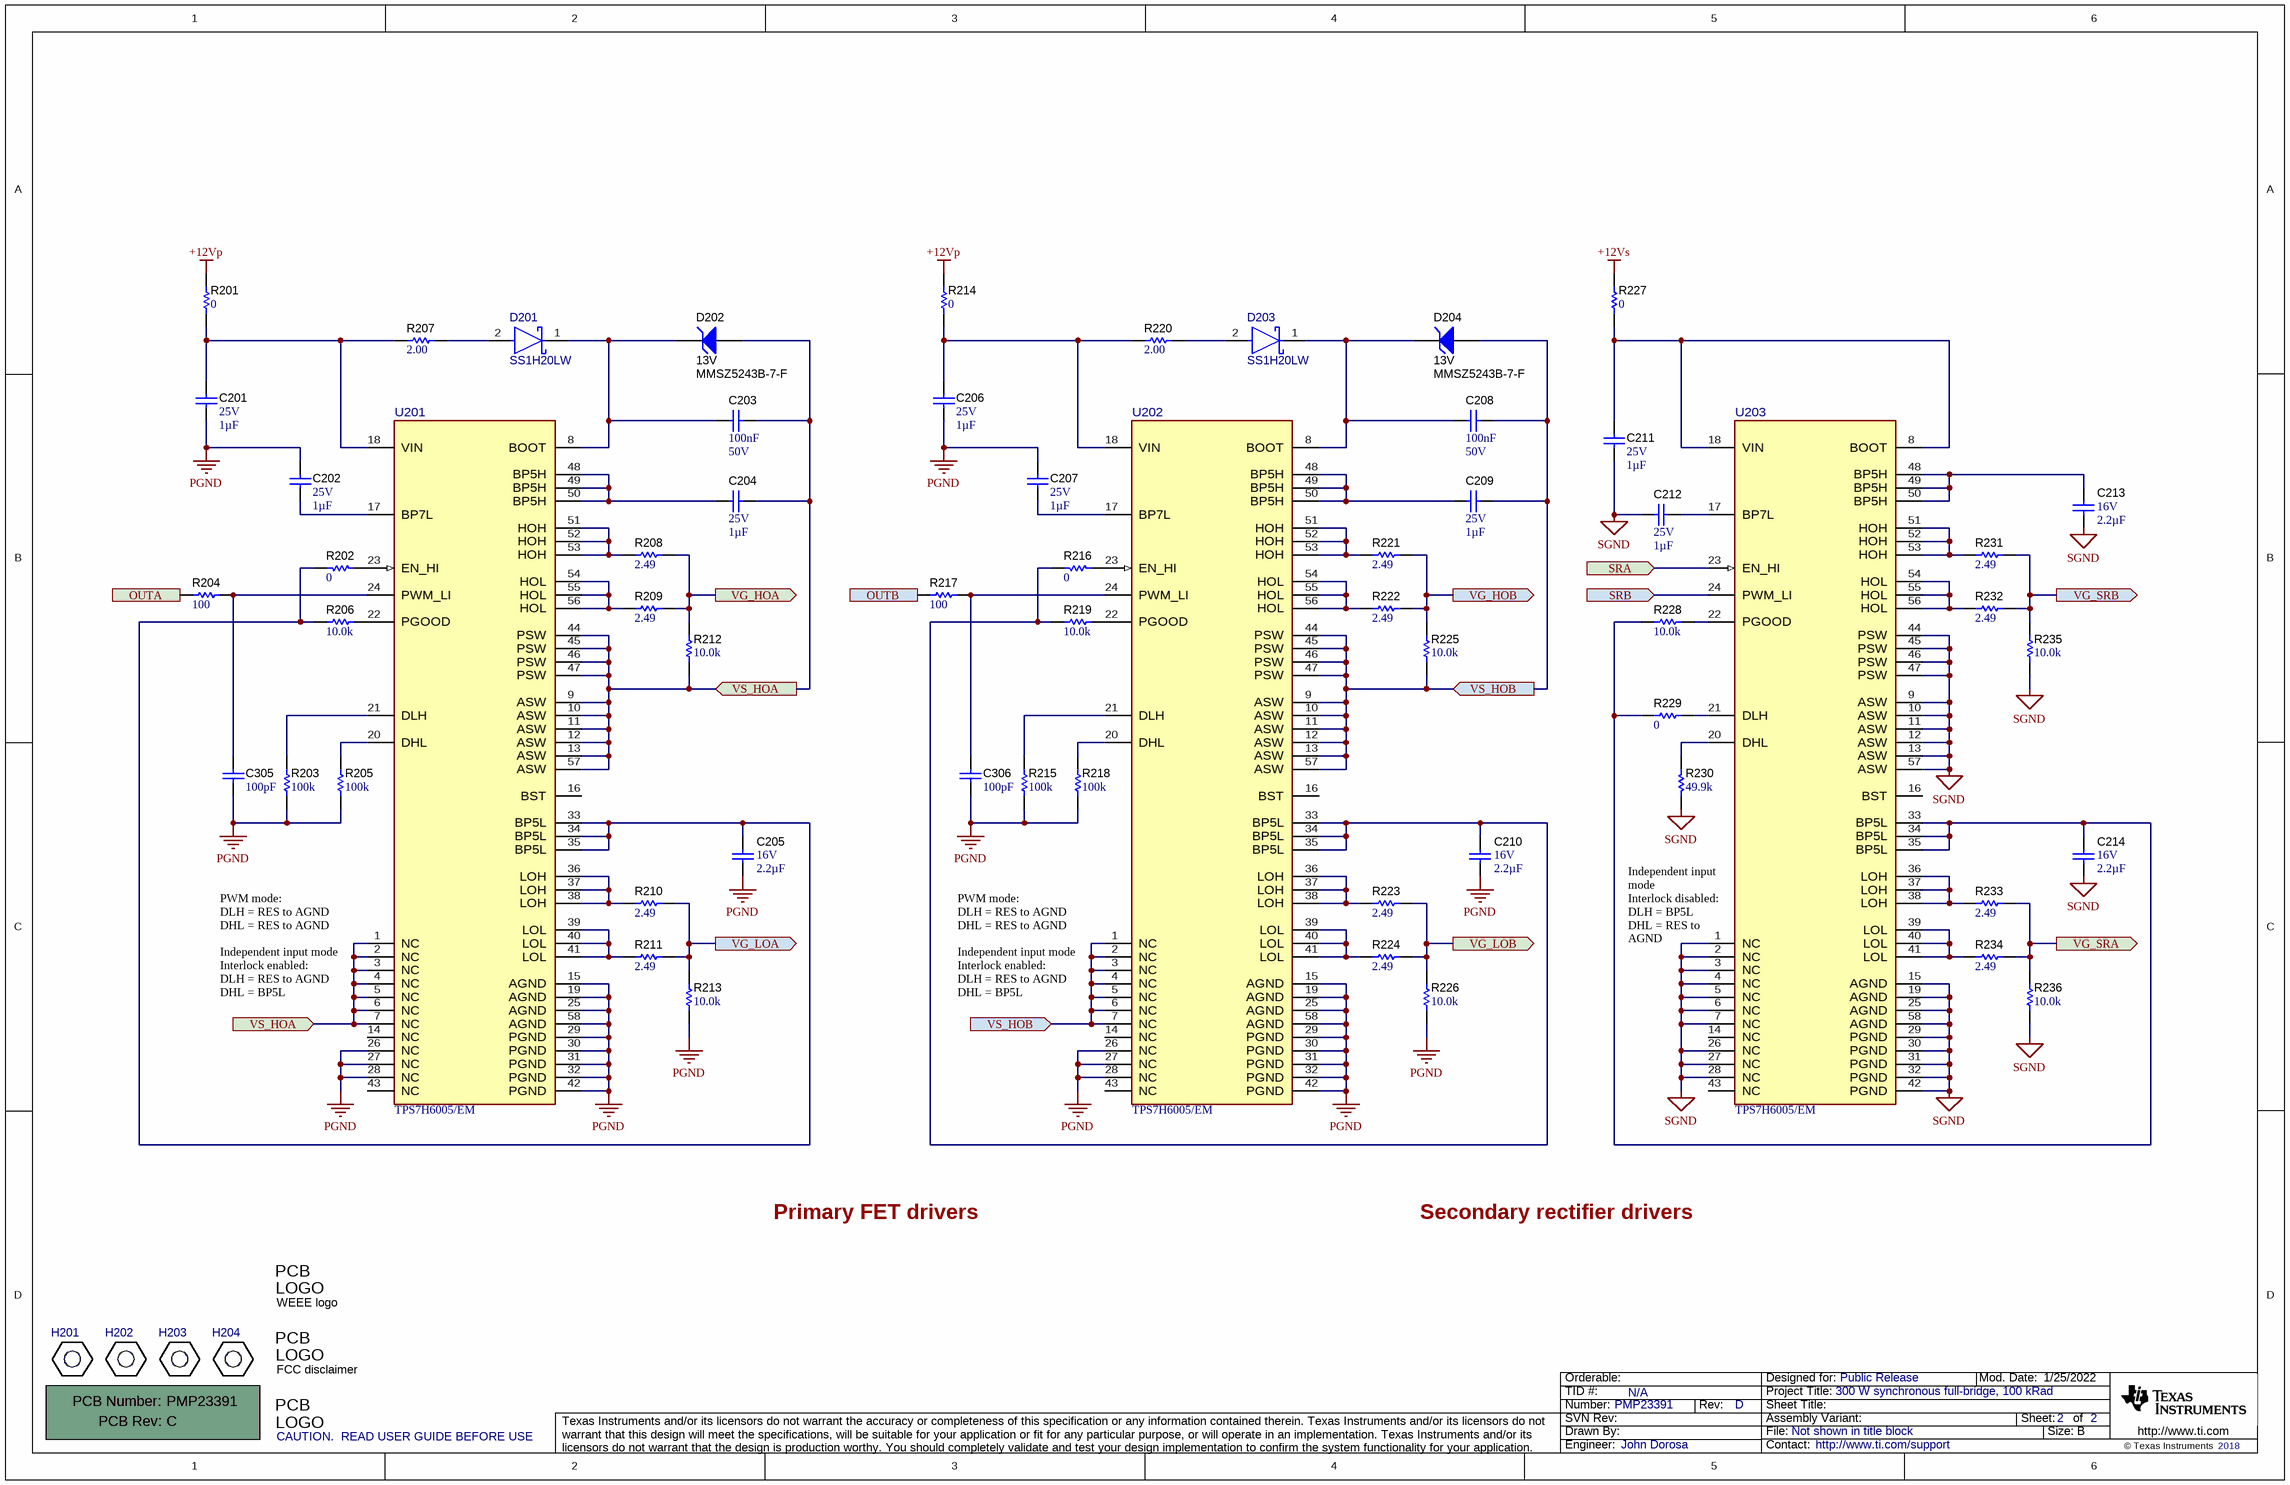
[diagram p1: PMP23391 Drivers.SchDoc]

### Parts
!PCB201  Printed Circuit Board  (value not drawn)  (mechanical)
C201  VDC_V: 25V  Cap_F: 1µF  [0603_HV]  (hidden comment: GRM188R71E105KA12D)
C202  VDC_V: 25V  Cap_F: 1µF  [0603_HV]  (hidden comment: GRM188R71E105KA12D)
C203  Cap_F: 100nF  VDC_V: 50V  [0603_HV]  (hidden comment: C0603C104K5RACAUTO)
C204  VDC_V: 25V  Cap_F: 1µF  [0603_HV]  (hidden comment: GRM188R71E105KA12D)
C205  VDC_V: 16V  Cap_F: 2.2µF  [0603_HV]  (hidden comment: GRM188Z71C225KE43)
C206  VDC_V: 25V  Cap_F: 1µF  [0603_HV]  (hidden comment: GRM188R71E105KA12D)
C207  VDC_V: 25V  Cap_F: 1µF  [0603_HV]  (hidden comment: GRM188R71E105KA12D)
C208  Cap_F: 100nF  VDC_V: 50V  [0603_HV]  (hidden comment: C0603C104K5RACAUTO)
C209  VDC_V: 25V  Cap_F: 1µF  [0603_HV]  (hidden comment: GRM188R71E105KA12D)
C210  VDC_V: 16V  Cap_F: 2.2µF  [0603_HV]  (hidden comment: GRM188Z71C225KE43)
C211  VDC_V: 25V  Cap_F: 1µF  [0603_HV]  (hidden comment: GRM188R71E105KA12D)
C212  VDC_V: 25V  Cap_F: 1µF  [0603_HV]  (hidden comment: GRM188R71E105KA12D)
C213  VDC_V: 16V  Cap_F: 2.2µF  [0603_HV]  (hidden comment: GRM188Z71C225KE43)
C214  VDC_V: 16V  Cap_F: 2.2µF  [0603_HV]  (hidden comment: GRM188Z71C225KE43)
C305  ValueDisplayed: 100pF  [0603_HV]  (hidden comment: GRM1885C1H101JA01D)
C306  ValueDisplayed: 100pF  [0603_HV]  (hidden comment: GRM1885C1H101JA01D)
D201  SS1H20LW  [FP-SS1H20LW_SOD-123W-MFG]
D202  MMSZ5243B-7-F  value 13V  [SOD-123]
D203  SS1H20LW  [FP-SS1H20LW_SOD-123W-MFG]
D204  MMSZ5243B-7-F  value 13V  [SOD-123]
H201  4824  [KEYSTONE_4824]  (value not drawn)
H202  4824  [KEYSTONE_4824]  (value not drawn)
H203  4824  [KEYSTONE_4824]  (value not drawn)
H204  4824  [KEYSTONE_4824]  (value not drawn)
Logo201  WEEE logo  [WEEE_Minimum]  (no BOM)
Logo202  FCC disclaimer  [FCC_disclaimer]  (no BOM)
Logo203  CAUTION.  READ USER GUIDE BEFORE USE  [IEC_Caution_Small]  (no BOM)
R201  ValueDisplayed: 0  [0603_HV]  (hidden comment: CRCW06030000Z0EA)
R202  ValueDisplayed: 0  [0603_HV]  (hidden comment: CRCW06030000Z0EA)
R203  ValueDisplayed: 100k  [0603_HV]  (hidden comment: CRCW0603100KFKEA)
R204  ValueDisplayed: 100  [0603_HV]  (hidden comment: CRCW0603100RJNEA)
R205  ValueDisplayed: 100k  [0603_HV]  (hidden comment: CRCW0603100KFKEA)
R206  ValueDisplayed: 10.0k  [0603_HV]  (hidden comment: CRCW060310K0FKEA)
R207  ValueDisplayed: 2.00  [0603_HV]  (hidden comment: MCT06030C2008FP500)
R208  ValueDisplayed: 2.49  [0603_HV]  (hidden comment: CRCW06032R49FKEA)
R209  ValueDisplayed: 2.49  [0603_HV]  (hidden comment: CRCW06032R49FKEA)
R210  ValueDisplayed: 2.49  [0603_HV]  (hidden comment: CRCW06032R49FKEA)
R211  ValueDisplayed: 2.49  [0603_HV]  (hidden comment: CRCW06032R49FKEA)
R212  ValueDisplayed: 10.0k  [0603_HV]  (hidden comment: CRCW060310K0FKEA)
R213  ValueDisplayed: 10.0k  [0603_HV]  (hidden comment: CRCW060310K0FKEA)
R214  ValueDisplayed: 0  [0603_HV]  (hidden comment: CRCW06030000Z0EA)
R215  ValueDisplayed: 100k  [0603_HV]  (hidden comment: CRCW0603100KFKEA)
R216  ValueDisplayed: 0  [0603_HV]  (hidden comment: CRCW06030000Z0EA)
R217  ValueDisplayed: 100  [0603_HV]  (hidden comment: CRCW0603100RJNEA)
R218  ValueDisplayed: 100k  [0603_HV]  (hidden comment: CRCW0603100KFKEA)
R219  ValueDisplayed: 10.0k  [0603_HV]  (hidden comment: CRCW060310K0FKEA)
R220  ValueDisplayed: 2.00  [0603_HV]  (hidden comment: MCT06030C2008FP500)
R221  ValueDisplayed: 2.49  [0603_HV]  (hidden comment: CRCW06032R49FKEA)
R222  ValueDisplayed: 2.49  [0603_HV]  (hidden comment: CRCW06032R49FKEA)
R223  ValueDisplayed: 2.49  [0603_HV]  (hidden comment: CRCW06032R49FKEA)
R224  ValueDisplayed: 2.49  [0603_HV]  (hidden comment: CRCW06032R49FKEA)
R225  ValueDisplayed: 10.0k  [0603_HV]  (hidden comment: CRCW060310K0FKEA)
R226  ValueDisplayed: 10.0k  [0603_HV]  (hidden comment: CRCW060310K0FKEA)
R227  ValueDisplayed: 0  [0603_HV]  (hidden comment: CRCW06030000Z0EA)
R228  ValueDisplayed: 10.0k  [0603_HV]  (hidden comment: CRCW060310K0FKEA)
R229  ValueDisplayed: 0  [0603_HV]  (hidden comment: CRCW06030000Z0EA)
R230  ValueDisplayed: 49.9k  [0603_HV]  (hidden comment: CRCW060349K9FKEA)
R231  ValueDisplayed: 2.49  [0603_HV]  (hidden comment: CRCW06032R49FKEA)
R232  ValueDisplayed: 2.49  [0603_HV]  (hidden comment: CRCW06032R49FKEA)
R233  ValueDisplayed: 2.49  [0603_HV]  (hidden comment: CRCW06032R49FKEA)
R234  ValueDisplayed: 2.49  [0603_HV]  (hidden comment: CRCW06032R49FKEA)
R235  ValueDisplayed: 10.0k  [0603_HV]  (hidden comment: CRCW060310K0FKEA)
R236  ValueDisplayed: 10.0k  [0603_HV]  (hidden comment: CRCW060310K0FKEA)
U201  TPS7H6005/EM  [DCA0056M-MFG]
U202  TPS7H6005/EM  [DCA0056M-MFG]
U203  TPS7H6005/EM  [DCA0056M-MFG]

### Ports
OUTA (in), OUTB (in), SRA (in), SRB (in), VG_HOA (out), VG_HOB (out), VG_LOA (out), VG_LOB (out), VG_SRA (out), VG_SRB (out), VS_HOA (in), VS_HOB (in)

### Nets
+12Vp: R201.1 R214.1
+12Vs: R227.1
PGND: C201.2 C202.1 C205.1 C206.2 C207.1 C210.1 C305.1 C306.1 R203.1 R205.1 R213.2 R215.1 R218.1 R226.2 U201.15(AGND) U201.19(AGND) U201.25(AGND) U201.26(NC) U201.27(NC) U201.28(NC) U201.29(PGND) U201.30(PGND) U201.31(PGND) U201.32(PGND) U201.42(PGND) U201.58(AGND) U202.15(AGND) U202.19(AGND) U202.25(AGND) U202.26(NC) U202.27(NC) U202.28(NC) U202.29(PGND) U202.30(PGND) U202.31(PGND) U202.32(PGND) U202.42(PGND) U202.58(AGND)
SGND: C211.2 C212.1 C213.1 C214.1 R230.2 R235.2 R236.2 U203.1(NC) U203.2(NC) U203.3(NC) U203.4(NC) U203.5(NC) U203.6(NC) U203.7(NC) U203.9(ASW) U203.10(ASW) U203.11(ASW) U203.12(ASW) U203.13(ASW) U203.15(AGND) U203.19(AGND) U203.25(AGND) U203.26(NC) U203.27(NC) U203.28(NC) U203.29(PGND) U203.30(PGND) U203.31(PGND) U203.32(PGND) U203.42(PGND) U203.44(PSW) U203.45(PSW) U203.46(PSW) U203.47(PSW) U203.57(ASW) U203.58(AGND)
OUTA: R204.2 ; port OUTA
OUTB: R217.2 ; port OUTB
SRA: U203.23(EN_HI) ; port SRA
SRB: U203.24(PWM_LI) ; port SRB
VG_HOA: R208.1 R209.1 R212.1 ; port VG_HOA
VG_HOB: R221.1 R222.1 R225.1 ; port VG_HOB
VG_LOA: R210.1 R211.1 R213.1 ; port VG_LOA
VG_LOB: R223.1 R224.1 R226.1 ; port VG_LOB
VG_SRA: R233.1 R234.1 R236.1 ; port VG_SRA
VG_SRB: R231.1 R232.1 R235.1 ; port VG_SRB
VS_HOA: C203.2 C204.2 D202.2(A) R212.2 U201.1(NC) U201.2(NC) U201.3(NC) U201.4(NC) U201.5(NC) U201.6(NC) U201.7(NC) U201.9(ASW) U201.10(ASW) U201.11(ASW) U201.12(ASW) U201.13(ASW) U201.44(PSW) U201.45(PSW) U201.46(PSW) U201.47(PSW) U201.57(ASW) ; port VS_HOA
VS_HOB: C208.2 C209.2 D204.2(A) R225.2 U202.1(NC) U202.2(NC) U202.3(NC) U202.4(NC) U202.5(NC) U202.6(NC) U202.7(NC) U202.9(ASW) U202.10(ASW) U202.11(ASW) U202.12(ASW) U202.13(ASW) U202.44(PSW) U202.45(PSW) U202.46(PSW) U202.47(PSW) U202.57(ASW) ; port VS_HOB
NetC201_1: C201.1 R201.2 R207.1 U201.18(VIN)
NetC202_2: C202.2 U201.17(BP7L)
NetC203_1: C203.1 D201.1(CATHODE) D202.1(K) U201.8(BOOT)
NetC204_1: C204.1 U201.48(BP5H) U201.49(BP5H) U201.50(BP5H)
NetC205_2: C205.2 R202.1 R206.2 U201.33(BP5L) U201.34(BP5L) U201.35(BP5L)
NetC206_1: C206.1 R214.2 R220.1 U202.18(VIN)
NetC207_2: C207.2 U202.17(BP7L)
NetC208_1: C208.1 D203.1(CATHODE) D204.1(K) U202.8(BOOT)
NetC209_1: C209.1 U202.48(BP5H) U202.49(BP5H) U202.50(BP5H)
NetC210_2: C210.2 R216.1 R219.2 U202.33(BP5L) U202.34(BP5L) U202.35(BP5L)
NetC211_1: C211.1 R227.2 U203.8(BOOT) U203.18(VIN)
NetC212_2: C212.2 U203.17(BP7L)
NetC213_2: C213.2 U203.48(BP5H) U203.49(BP5H) U203.50(BP5H)
NetC214_2: C214.2 R228.2 R229.1 U203.33(BP5L) U203.34(BP5L) U203.35(BP5L)
NetC305_2: C305.2 R204.1 U201.24(PWM_LI)
NetC306_2: C306.2 R217.1 U202.24(PWM_LI)
NetD201_2: D201.2(ANODE) R207.2
NetD203_2: D203.2(ANODE) R220.2
NetR202_2: R202.2 U201.23(EN_HI)
NetR203_2: R203.2 U201.21(DLH)
NetR205_2: R205.2 U201.20(DHL)
NetR206_1: R206.1 U201.22(PGOOD)
NetR208_2: R208.2 U201.51(HOH) U201.52(HOH) U201.53(HOH)
NetR209_2: R209.2 U201.54(HOL) U201.55(HOL) U201.56(HOL)
NetR210_2: R210.2 U201.36(LOH) U201.37(LOH) U201.38(LOH)
NetR211_2: R211.2 U201.39(LOL) U201.40(LOL) U201.41(LOL)
NetR215_2: R215.2 U202.21(DLH)
NetR216_2: R216.2 U202.23(EN_HI)
NetR218_2: R218.2 U202.20(DHL)
NetR219_1: R219.1 U202.22(PGOOD)
NetR221_2: R221.2 U202.51(HOH) U202.52(HOH) U202.53(HOH)
NetR222_2: R222.2 U202.54(HOL) U202.55(HOL) U202.56(HOL)
NetR223_2: R223.2 U202.36(LOH) U202.37(LOH) U202.38(LOH)
NetR224_2: R224.2 U202.39(LOL) U202.40(LOL) U202.41(LOL)
NetR228_1: R228.1 U203.22(PGOOD)
NetR229_2: R229.2 U203.21(DLH)
NetR230_1: R230.1 U203.20(DHL)
NetR231_2: R231.2 U203.51(HOH) U203.52(HOH) U203.53(HOH)
NetR232_2: R232.2 U203.54(HOL) U203.55(HOL) U203.56(HOL)
NetR233_2: R233.2 U203.36(LOH) U203.37(LOH) U203.38(LOH)
NetR234_2: R234.2 U203.39(LOL) U203.40(LOL) U203.41(LOL)

Not connected (* = marked no-connect by the designer): U201 14(NC) 16(BST) 43(NC); U202 14(NC) 16(BST) 43(NC); U203 14(NC) 16(BST) 43(NC)

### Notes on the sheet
- PWM mode:
  DLH = RES to AGND
  DHL = RES to AGND
- (near U203) Independent input mode
  Interlock disabled:
  DLH = BP5L
  DHL = RES to AGND
- Independent input mode
  Interlock enabled:
  DLH = RES to AGND
  DHL = BP5L
- Primary FET drivers
- Secondary rectifier drivers

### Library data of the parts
!PCB201 = CMP-0003618-2: Manufacturer: Any; PartNumber: PMP23391
C201 C202 C204 C206 C207 C209 C211 C212 = CMP-0007405-5: as C101 on sheet PMP23391 Power Stage
C203 C208 = CMP-0079602-1: CAP, CERM, 0.1 µF, 50 V,+/- 10%, X7R, AEC-Q200 Grade 1, 0603; Manufacturer: Kemet; TaMin_C: -55°C; Polarized: N; SizeAreaWB_mm2: 4.68; U/M: EA; Value: 0.1uF; TaMax_C: 125°C; SizeZ_mm: 1; SizeX_mm: 1.6; SizeY_mm: 0.8; Cap_Case: 0603; SizeArea_mm2: 1.28; AEC Qualified: Y; AEC Category: Q200; ValueDisplayed: 0.1µF
C205 C210 C213 C214 = CMP-0007499-4: as C104 on sheet PMP23391 Power Stage
C305 C306 = CMP-0007171-4: as C113 on sheet PMP23391 Power Stage
D201 D203 = CMP-0095320-1: Diode Schottky 200 V 1A Surface Mount SOD-123W; Manufacturer: Taiwan Semiconductor; Max Surge Forward Current: 30A; SizeZ_mm: 1.02mm; AEC Qualified: No; Vf_V: 200V; TJmax_C: 175°C; Peak Reverse Current: 0.1mA; Standoff Height: 0mm
D202 D204 = CMP-0005752-4: Diode, Zener, 13 V, 500 mW, SOD-123; Manufacturer: Diodes Inc.; Value1: 0.5W; SizeAreaWB_mm2: 13.095; RJA_CperW: 350; AEC Category: Q101; SizeZ_mm: 1.35; SizeX_mm: 3.85; Power_W: 500mW; SizeArea_mm2: 6.545; SizeY_mm: 1.7
H201-H204 = CMP-0003690-1: Manufacturer: Keystone; CompType: Standoff
Logo201 = CMP-0074769-1
Logo202 = CMP-0074847-1: FCC_disclaimer; Library Reference: Logo
Logo203 = CMP-0074836-1: IEC 61010-1 Caution Warning; SymbolCreator: a0412235; Lib Reference: IEC_Caution
R201 R202 R214 R216 R227 R229 = CMP-0025697-4: as R107 on sheet PMP23391 Power Stage
R203 R205 R215 R218 = CMP-0021990-4: RES, 100 k, 1%, 0.1 W, AEC-Q200 Grade 0, 0603; Manufacturer: Vishay-Dale; Power_W: 100mW; TempCo: 100 ppm/C; Value: 100k; EIA_Code: E96; SizeX_mm: 1.6; SizeY_mm: 0.8; SizeZ_mm: 1; Value2: 0.1W; SizeArea_mm2: 1.28; AEC Qualified: Y; VDC_V: 75V; AEC Category: Q200; AEC Grade: 0
R204 R217 = CMP-0025700-4: as R113 on sheet PMP23391 Power Stage
R206 R212 R213 R219 R225 R226 R228 R235 R236 = CMP-0021998-4: as R122 on sheet PMP23391 Power Stage
R207 R220 = CMP-0022732-2: RES, 2.00, 1%, 0.125 W, 0603; Manufacturer: Vishay/Beyschlag; Power_W: 125mW; TempCo: 50 ppm/C; Value_Code: 2R00; U/M: EA; Value: 2.00; EIA_Code: E96; Res_ohm: 2; SizeX_mm: 1.6; SizeY_mm: 0.8; Value2: 0.125W; SizeArea_mm2: 1.28; AEC Qualified: N; AEC Category: Q200; SizeZ_mm: 1
R208-R211 R221-R224 R231-R234 = CMP-0022311-4: RES, 2.49, 1%, 0.1 W, AEC-Q200 Grade 0, 0603; Manufacturer: Vishay-Dale; Power_W: 100mW; TempCo: 100 ppm/C; Value_Code: 2R49; Value: 2.49; EIA_Code: E96; SizeX_mm: 1.6; SizeY_mm: 0.8; SizeZ_mm: 1; Value2: 0.1W; SizeArea_mm2: 1.28; AEC Qualified: Y; VDC_V: 75V; AEC Category: Q200; AEC Grade: 0
R230 = CMP-0022447-4: as R104 on sheet PMP23391 Power Stage
U201-U203 = CMP-0120202-4: Manufacturer: Texas Instruments; SizeZ_mm: 1.2mm; Standoff Height: 0.05mm; AEC Category: Q200; CompType: IC

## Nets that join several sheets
+12Vp: PMP23391 Power Stage (J102.5), PMP23391 Drivers (R201.1 R214.1)
+12Vs: PMP23391 Power Stage (D111.1 D112.1 J104.1 R107.2), PMP23391 Drivers (R227.1)
PGND: PMP23391 Power Stage (17 pins), PMP23391 Drivers (38 pins)
SGND: PMP23391 Power Stage (57 pins), PMP23391 Drivers (36 pins)
OUTA: PMP23391 Power Stage (D113.1 Q109.2), PMP23391 Drivers (R204.2)
OUTB: PMP23391 Power Stage (D114.1 Q110.2), PMP23391 Drivers (R217.2)
SRA: PMP23391 Power Stage (C114.2 D108.1 R114.1), PMP23391 Drivers (U203.23)
SRB: PMP23391 Power Stage (C113.2 D105.1 R113.1), PMP23391 Drivers (U203.24)
VG_HOA: PMP23391 Power Stage (Q101.1), PMP23391 Drivers (R208.1 R209.1 R212.1)
VG_HOB: PMP23391 Power Stage (Q103.1), PMP23391 Drivers (R221.1 R222.1 R225.1)
VG_LOA: PMP23391 Power Stage (Q102.1), PMP23391 Drivers (R210.1 R211.1 R213.1)
VG_LOB: PMP23391 Power Stage (Q104.1), PMP23391 Drivers (R223.1 R224.1 R226.1)
VG_SRA: PMP23391 Power Stage (Q105.1), PMP23391 Drivers (R233.1 R234.1 R236.1)
VG_SRB: PMP23391 Power Stage (Q106.1), PMP23391 Drivers (R231.1 R232.1 R235.1)
VS_HOA: PMP23391 Power Stage (Q101.5), PMP23391 Drivers (21 pins)
VS_HOB: PMP23391 Power Stage (Q103.5), PMP23391 Drivers (21 pins)

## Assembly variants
001: not fitted R108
